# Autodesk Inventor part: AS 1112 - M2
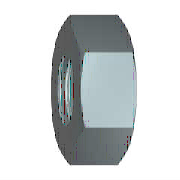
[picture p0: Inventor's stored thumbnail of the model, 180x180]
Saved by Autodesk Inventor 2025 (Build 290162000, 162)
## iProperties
Created: 2024-01
Part Number: AS 1112 - M2
Material: Acciaio, Dolce
Description: Dadi esagonali metrici ISO, inclusi dadi sottili, dadi con intaglio e dadi a corona
Document SubType Name: Modeling
Standard: AS 1112
Designer: Ryzen5700u
Standards Organization: AS
Language: it-IT
Size Designation: M2
Categories: <MemberInstance><Categories><Category DisplayName="Elementi di fissaggio" InternalName="e4da775c-781d-43d5-af7c-5136215cf5a6" Mnemonic="FSTN"><Category DisplayN
Density: 7.85 g/cm^3
Appearance: Semilucidato
IsCustomPart: 0
Author: Ryzen5700u
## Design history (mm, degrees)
workaxis "Work Axis1"
workplane "Work Plane1"
body "Solid1"
sketch "Schizzo1"
  geometry: L1 (-2.309, 0)-(-1.155, 2); L2 (-1.155, 2)-(1.155, 2); L3 (1.155, 2)-(2.309, 0); L4 (2.309, 0)-(1.155, -2); L5 (1.155, -2)-(-1.155, -2); L6 (-1.155, -2)-(-2.309, 0); 2 further points
  constraints: 12 end point, 1 coincident, 1 horizontal, 11 other
  dimensions: "d0" = 4.6188 distance of L3.end L1.start (= 1.1547 x SW)
extrude "Corpo" new body sketch "Schizzo1" distance "d1" = 1.2 (= KOH); taper "d2" = 0 deg
revolve "Smusso1" stored, may be unused: angle "d7" = 90 deg
sketch "Schizzo3"
  geometry: A1 r 2 centre (0, 0) between (-1, -1.732) and (1, -1.732) reference; 1 further point
  constraints: 1 coincident
hole "Filettatura" sketch "Schizzo3" diameter "d25" = 1.567; stored, may be unused: countersink angle "d29" = 82 deg, drill point angle "d31" = 118 deg; dims "d26" = 6, "d27" = 4, "d28" = 2, "d30" = 8
chamfer "Smusso2" distance "d8" = 0.21651 (= -0.5 x GD1 + 0.5 x NND); stored, may be unused: angle "d9" = 30 deg, second distance "d40" = 0.21651 (= -0.5 x GD1 + 0.5 x NND)
chamfer "Smusso3" distance "d10" = 0.21651 (= -0.5 x GD1 + 0.5 x NND); stored, may be unused: angle "d11" = 30 deg, second distance "d41" = 0.21651 (= -0.5 x GD1 + 0.5 x NND)
sketch "Schizzo2"
  geometry: L1 (0, 1.155)-(0, 2.309) reference; L2 (0, 2.309)-(1.2, 2.309) reference; L3 (1.2, 1.155)-(1.2, 2.309) reference; L4 (-0.24, 0)-(1.44, 0) reference; L5 (0.179, 2.309)-(0, 2); L6 (1.021, 2.309)-(1.2, 2)
  constraints: 4 end point, 4 point on line
  dimensions: "d3" = 30 deg angle of L1 L5 (= ANG1); "d4" = 30 deg angle of L3 L6 (= ANG2); "d5" = 4 diameter of L5.end L4 (= SW0); "d6" = 4 diameter of L6.end L4 (= SW01)
other parameters: "ANG1" = 30 deg [user parameter; used in 1 equation term], "ANG2" = 30 deg [user parameter; used in 1 equation term], "NND" = 2 [user parameter; used in 4 equation terms], "KOH" = 1.2 [user parameter; used in 1 equation term], "SW" = 4 [user parameter; used in 4 equation terms], "SW0" = 4 (= SW) [user parameter; used in 1 equation term], "SW01" = 4 (= SW) [user parameter; used in 1 equation term], "GD1" = 1.56699 (computed from THREADDIA, PTC, TOA) [user parameter; used in 4 equation terms], "d13" = 0, "d14" = 0, "d39" = 0, "d42" = 0, "GUL" = 0.21651 (= 0.541266 x PTC) [user parameter], "TPU" = 25 (computed from PTC) [user parameter], "THREADDIA" = 2 [user parameter; used in 1 equation term], "TOA" = 30 deg [user parameter; used in 1 equation term], "PTC" = 0.4 [user parameter; used in 4 equation terms], "E0" = 4.62 (= 1.155 x SW) [user parameter], "GAL" = 0.21651 (= 0.541266 x PTC) [user parameter]
